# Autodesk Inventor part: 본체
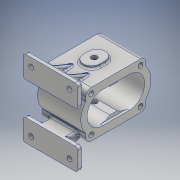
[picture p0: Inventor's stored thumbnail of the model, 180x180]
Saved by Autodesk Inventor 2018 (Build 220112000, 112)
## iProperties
Created: 2023-06
Part Number: 본체
Material: 알루미늄 6061
Document SubType Name: Modeling
Designer: home
Density: 2.7 g/cm^3
Appearance: 알루미늄 - 평지
Mass: 1266.81 g
Surface Area: 985.292 cm^2
Volume: 469.189 cm^3
Author: home
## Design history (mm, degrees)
sketch "스케치1"
  geometry: L1 (-45, 70)-(45, 70); L2 (50, 65)-(50, 35); L3 (45, 30)-(-45, 30); L4 (-50, 35)-(-50, 65); L5 (-50, 70)-(50, 30); L6 (50, 70)-(-50, 30); L7 (-45, -30)-(45, -30); L8 (50, -35)-(50, -65); L9 (45, -70)-(-45, -70); L10 (-50, -65)-(-50, -35); L11 (-50, -30)-(50, -70); L12 (50, -30)-(-50, -70); A1 r 5 centre (45, 65) between (50, 65) and (45, 70); A2 r 5 centre (45, 35) between (45, 30) and (50, 35); A3 r 5 centre (-45, 35) between (-50, 35) and (-45, 30); A4 r 5 centre (-45, 65) between (-45, 70) and (-50, 65); A5 r 5 centre (-45, -35) between (-45, -30) and (-50, -35); A6 r 5 centre (-45, -65) between (-50, -65) and (-45, -70); A7 r 5 centre (45, -65) between (45, -70) and (50, -65); A8 r 5 centre (45, -35) between (50, -35) and (45, -30); 5 further points
  constraints: 24 end point, 16 point on circle, 16 point on line, 16 tangent, 8 centre point, 7 equal radius, 6 midpoint, 4 parallel, 2 horizontal, 2 perpendicular, 2 vertical alignment
  dimensions: "d0" = 100 distance of L5.end L6.end; "d1" = 40 distance of L6.start L5.end; "d2" = 100 distance of L11.end L12.end; "d3" = 40 distance of L12.start L11.end; "d6" = 5 radius of A1; "d35" = 140 distance between parallel lines of L9 L1; "d37" = 70 distance from line of point (0, 0) L1
extrude "돌출1" new body sketch "스케치1" distance "d7" = 9; taper "d8" = 0 deg
sketch "스케치2"
  geometry: L1 (35, 42.5)-(125, 42.5); L2 (135, 32.5)-(135, -32.5); L3 (125, -42.5)-(35, -42.5); L4 (25, -32.5)-(25, 32.5); L5 (25, 42.5)-(135, -42.5); L6 (135, 42.5)-(25, -42.5); L7 (86.507, -22.5)-(73.493, -22.5); L8 (86.507, 22.5)-(73.493, 22.5); A1 r 28.5 centre (104, 0) between (86.507, -22.5) and (86.507, 22.5); A2 r 28.5 centre (56, 0) between (73.493, 22.5) and (73.493, -22.5); A3 r 40 centre (56, 0) between (25, 25.278) and (25, -25.278); A4 r 40 centre (104, 0) between (135, -25.278) and (135, 25.278); A5 r 10 centre (125, 32.5) between (135, 32.5) and (125, 42.5); A6 r 10 centre (125, -32.5) between (125, -42.5) and (135, -32.5); A7 r 10 centre (35, -32.5) between (25, -32.5) and (35, -42.5); A8 r 10 centre (35, 32.5) between (35, 42.5) and (25, 32.5); 4 further points
  constraints: 16 end point, 16 point on circle, 12 point on line, 8 centre point, 8 tangent, 4 midpoint, 3 equal radius, 3 horizontal, 3 horizontal alignment, 2 coincident, 2 parallel, 1 perpendicular
  dimensions: "d9" = 110 distance of L5.end L6.end; "d10" = 85 distance of L6.start L5.end; "d11" = 80 distance of point (0, 0) point (80, 0); "d12" = 28.5 radius of A1; "d14" = 24 distance of A1.centre point (80, 0); "d15" = 24 distance of point (80, 0) A2.centre; "d16" = 22.5 distance from line of L7 point (80, 0); "d17" = 22.5 distance from line of L8 point (80, 0); "d18" = 28.5 radius of A2; "d19" = 40 radius of A3; "d20" = 40 radius of A4; "d21" = 10 radius of A5
extrude "돌출2" join sketch "스케치2" stored distance "d22" = 79; taper "d23" = 0 deg
sketch "스케치3"
  geometry: L1 (-22.5, 73.493)-(-22.5, 86.507) reference; L2 (22.5, 86.507)-(22.5, 73.493) reference; L3 (25.278, 25)-(32.5, 25) reference; L4 (42.5, 35)-(42.5, 125) reference; L5 (32.5, 135)-(25.278, 135) reference; L6 (-25.278, 135)-(-32.5, 135) reference; L7 (-42.5, 125)-(-42.5, 35) reference; L8 (-32.5, 25)-(-25.278, 25) reference; A1 r 28.5 centre (0, 56) between (-22.5, 73.493) and (22.5, 73.493) reference; A2 r 28.5 centre (0, 104) between (22.5, 86.507) and (-22.5, 86.507) reference; A3 r 40 centre (0, 56) between (-25.278, 25) and (25.278, 25) reference; A4 r 10 centre (32.5, 35) between (32.5, 25) and (42.5, 35) reference; A5 r 10 centre (32.5, 125) between (42.5, 125) and (32.5, 135) reference; A6 r 40 centre (0, 104) between (25.278, 135) and (-25.278, 135) reference; A7 r 10 centre (-32.5, 125) between (-32.5, 135) and (-42.5, 125) reference; A8 r 10 centre (-32.5, 35) between (-42.5, 35) and (-32.5, 25) reference; 5 further points
  constraints: 4 coincident
hole "구멍1" sketch "스케치3" at (-32.5, 125), (32.5, 125), (32.5, 35), (-32.5, 35) diameter "d24" = 9; stored, may be unused: countersink angle "d28" = 90 deg, drill point angle "d30" = 118 deg; dims "d25" = 6, "d26" = 4, "d27" = 2, "d29" = 8
sketch "스케치4"
  geometry: L1 (-50, -65)-(-50, -35) reference; L2 (-45, -30)-(45, -30) reference; L3 (50, -35)-(50, -65) reference; L4 (45, -70)-(-45, -70) reference; L5 (50, 35)-(50, 65) reference; L6 (-45, 30)-(45, 30) reference; L7 (-50, 65)-(-50, 35) reference; L8 (45, 70)-(-45, 70) reference; L9 (-25, -34)-(25, -34); L10 (-21, -38)-(21, -38); L11 (21, -30)-(-21, -30); L12 (-25, 34)-(25, 34); L13 (-21, 30)-(21, 30); L14 (21, 38)-(-21, 38); A1 r 5 centre (-45, -35) between (-45, -30) and (-50, -35) reference; A2 r 5 centre (45, -35) between (50, -35) and (45, -30) reference; A3 r 5 centre (45, -65) between (45, -70) and (50, -65) reference; A4 r 5 centre (-45, -65) between (-50, -65) and (-45, -70) reference; A5 r 5 centre (45, 35) between (45, 30) and (50, 35) reference; A6 r 5 centre (-45, 35) between (-50, 35) and (-45, 30) reference; A7 r 5 centre (-45, 65) between (-45, 70) and (-50, 65) reference; A8 r 5 centre (45, 65) between (50, 65) and (45, 70) reference; A9 r 4 centre (-21, -34) between (-21, -30) and (-21, -38); A10 r 4 centre (21, -34) between (21, -38) and (21, -30); A11 r 4 centre (-21, 34) between (-21, 38) and (-21, 30); A12 r 4 centre (21, 34) between (21, 30) and (21, 38); 3 further points
  constraints: 16 end point, 12 point on circle, 8 tangent, 4 centre point, 4 point on line, 3 parallel, 2 collinear, 2 midpoint, 2 vertical alignment, 1 horizontal
  dimensions: "d31" = 50 distance of L9.start L9.end; "d32" = 4 radius of A10; "d33" = 50 distance of L12.start L12.end; "d34" = 4 radius of A12
extrude "돌출3" join sketch "스케치4" stored distance "d38" = 79; taper "d39" = 0 deg
node "작업 평면1"
sketch "스케치5"
  geometry: L1 (35, 42.5)-(125, 42.5) reference; L2 (9, 35)-(9, 65) reference; L3 (9, 62)-(54.939, 42.5); L4 (0, 70)-(9, 70) reference; 1 further point
  constraints: 2 end point, 2 point on line
  dimensions: "d41" = 23 deg angle of L3 L4; "d42" = 8 distance from line of L4 L3.start
feature "리브1" sketch "스케치5" dims "d43" = 1, "d44" = 7, "d45" = 0, "d46" = 0, "d47" = 1, "d48" = 1
sketch "스케치6"
  geometry: L1 (-45, 30)-(45, 30) reference; L2 (-50, 65)-(-50, 35) reference; L3 (45, 70)-(-45, 70) reference; L4 (50, 35)-(50, 65) reference; L5 (-45, -30)-(45, -30) reference; L6 (50, -35)-(50, -65) reference; L7 (45, -70)-(-45, -70) reference; L8 (-50, -65)-(-50, -35) reference; C1 r 9 at (35, -55); C2 r 9 at (-35, -55); C3 r 9 at (35, 55); C4 r 9 at (-35, 55); A1 r 5 centre (-45, 35) between (-50, 35) and (-45, 30) reference; A2 r 5 centre (-45, 65) between (-45, 70) and (-50, 65) reference; A3 r 5 centre (45, 65) between (50, 65) and (45, 70) reference; A4 r 5 centre (45, 35) between (45, 30) and (50, 35) reference; A5 r 5 centre (45, -35) between (50, -35) and (45, -30) reference; A6 r 5 centre (45, -65) between (45, -70) and (50, -65) reference; A7 r 5 centre (-45, -65) between (-50, -65) and (-45, -70) reference; A8 r 5 centre (-45, -35) between (-45, -30) and (-50, -35) reference; 1 further point
  constraints: 4 centre point, 1 horizontal, 1 vertical, 6 other
  dimensions: "d49" = 9 radius of C1; "d50" = 55 vertical distance of point (0, 0) C1.centre; "d51" = 35 horizontal distance of point (0, 0) C1.centre; "d54" = 70 distance of C1.centre C2.centre; "d57" = 110 distance of C1.centre C3.centre
extrude "돌출4" join sketch "스케치6" distance "d60" = 3; taper "d61" = 0 deg
sketch "스케치7"
  geometry: C1 r 9 at (-70, 0) reference; C2 r 9 at (0, 0) reference; C3 r 9 at (0, 110) reference; C4 r 9 at (-70, 110) reference; 5 further points
  constraints: 4 coincident
hole "구멍2" sketch "스케치7" at (-70, 0), (0, 0), (0, 110), (-70, 110) diameter "d62" = 9; stored, may be unused: countersink angle "d66" = 90 deg, drill point angle "d68" = 118 deg; dims "d63" = 6, "d64" = 4, "d65" = 2, "d67" = 8
sketch "스케치8"
  geometry: L1 (-28.5, 56)-(28.5, 56); L2 (28.5, 56)-(28.5, 104); L3 (28.5, 104)-(-28.5, 104); L4 (-28.5, 104)-(-28.5, 56); L5 (-28.5, 56)-(28.5, 104); L6 (28.5, 56)-(-28.5, 104); 3 further points
  constraints: 12 end point, 3 midpoint, 2 parallel, 1 horizontal, 1 perpendicular, 1 vertical alignment
  dimensions: "d69" = 57 distance of L3.end L2.end; "d70" = 48 distance of L2.end L1.end; "d71" = 80 distance of point (0, 0) point (0, 80)
extrude "돌출5" cut sketch "스케치8" distance "d72" = 4.5; taper "d73" = 0 deg
sketch "스케치9"
  geometry: L1 (84.5, -125)-(-5.5, -125) reference; L2 (54.5, -40)-(54.5, -50); L3 (24.5, -40)-(24.5, -50); A1 r 15 centre (39.5, -40) between (54.5, -40) and (24.5, -40); A2 r 15 centre (39.5, -50) between (24.5, -50) and (54.5, -50); 2 further points
  constraints: 4 end point, 4 point on circle, 2 centre point, 2 tangent, 2 vertical, 2 vertical alignment, 1 midpoint
  dimensions: "d74" = 15 radius of A1; "d75" = 15 radius of A2; "d76" = 75 distance from line of A2.centre L1; "d77" = 10 distance of A1.centre A2.centre
extrude "돌출6" join sketch "스케치9" distance "d78" = 5; taper "d79" = 0 deg
sketch "스케치10"
  geometry: L1 (84.5, -125)-(-5.5, -125) reference; C1 r 5 at (39.5, -45); 2 further points
  constraints: 1 centre point, 1 midpoint, 1 vertical alignment
  dimensions: "d80" = 5 radius of C1; "d81" = 80 distance from line of L1 C1.centre
extrude "돌출7" cut sketch "스케치10" stored distance "d82" = 5; taper "d83" = 0 deg
node "작업 평면2"
sketch "스케치12"
  geometry: 2 further points
  constraints: 1 horizontal alignment, 1 other
  dimensions: "d95" = 20 distance of point (0, 0) point (-20, 0)
feature "엠보싱1" sketch "스케치12" dims "d0" = 100, "d1" = 40, "d2" = 100, "d3" = 40, "d6" = 5, "d35" = 140, "d37" = 70, "d96" = 0.5, "d97" = 0
fillet "모깎기1" dims "d98" = 3
sketch "스케치13"
  geometry: L1 (-45, -75)-(45, -75) reference; 3 further points
  constraints: 1 midpoint, 1 vertical alignment
  dimensions: "d99" = 80 distance from line of L1 point (0, 5)
hole "구멍4" sketch "스케치13" at (0, 5) diameter "d100" = 10.5; stored, may be unused: countersink angle "d106" = 90 deg, drill point angle "d108" = 118 deg; dims "d101" = 11, "d102" = 0.62479, "d103" = 10.589, "d104" = 4, "d105" = 2, "d107" = 17.5
fillet "모깎기2" dims "d109" = 3
node "솔리드1"
mirror "미러1"
mirror "미러2"
mirror "미러3"
mirror "미러4"
node "투영된 루프1"
node "투영된 루프2"
node "투영된 루프3"
node "투영된 루프4"
node "투영된 루프5"
other parameters: "d13" = 28.5, "d40" = 14.5, "d94" = 144
